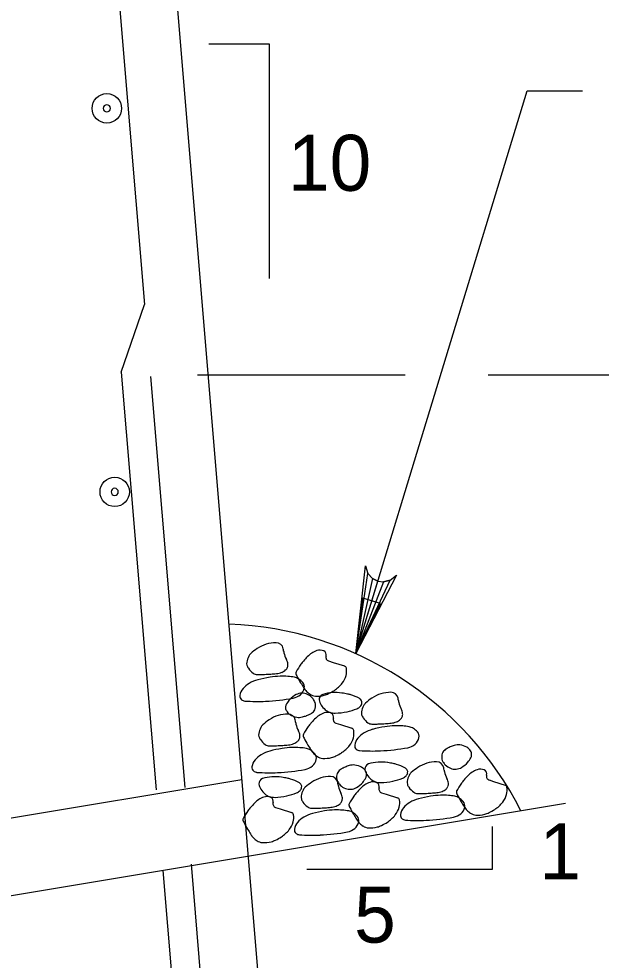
# Model space of a CAD drawing. Extents: x 634540 to 640306, y 296059 to 300275.
# Drawn here: x 639120.7 to 639151.9, y 297076.2 to 297126.7 of the extents above; entities that cross this region are included whole.
import ezdxf

# ---------------------------------------------------------------- set-up
doc = ezdxf.new("R2010")
doc.units = 0
for name, color, linetype in [('3', 7, 'Continuous'), ('5', 7, 'Continuous'), ('8', 7, 'Continuous'), ('9', 7, 'Continuous')]:
    doc.layers.add(name, color=color, linetype=linetype)

# ---------------------------------------------------------------- blocks, each defined once
blk = doc.blocks.new('B')
at = {"layer": '3'}
blk.add_circle((0, 0), 0.16, dxfattribs=at)
for start, end in [(0, 180), (180, 0)]:
    blk.add_arc((0, 0), 0.0391, start, end, dxfattribs=at)

msp = doc.modelspace()

# ---------------------------------------------------------------- linework, layer by layer
at = {"layer": '3'}
for p, q in [((639138.727, 297092.662), (639147.915, 297122.82)), ((639147.915, 297122.82), (639150.867, 297122.82)), ((639130.254, 297107.608), (639141.375, 297107.608)), ((639145.831, 297107.608), (639182.433, 297107.608))]:
    msp.add_line(p, q, dxfattribs=at)
for points in [[(639138.727, 297092.662), (639139.25, 297097.375), (639139.383, 297096.958), (639139.627, 297096.692), (639139.91, 297096.548), (639140.225, 297096.508), (639140.579, 297096.596), (639140.921, 297096.867), (639138.727, 297092.662), (639140.579, 297096.596), (639140.225, 297096.508), (639138.727, 297092.662), (639139.91, 297096.548), (639139.627, 297096.692), (639138.727, 297092.662), (639139.383, 297096.958)], [(639146.032, 297083.404), (639146.032, 297081.095), (639136.108, 297081.095)]]:
    msp.add_lwpolyline(points, dxfattribs=at)
msp.add_lwpolyline([(639140.058, 297095.344), (639139.117, 297095.629), (639138.727, 297092.662)], close=True, dxfattribs=at)
at = {"layer": '5'}
for p, q in [((639123.812, 297154.657), (639127.418, 297111.376)), ((639126.176, 297107.753), (639127.418, 297111.376)), ((639126.176, 297107.753), (639128.043, 297085.352)), ((639127.739, 297107.519), (639129.577, 297085.481)), ((639129.918, 297081.381), (639135.077, 297019.488)), ((639128.404, 297081.039), (639131.954, 297038.431))]:
    msp.add_line(p, q, dxfattribs=at)
at = {"layer": '8'}
for points in [[(639137.277, 297092.269), (639137.521, 297092.192), (639138.131, 297092)], [(639137.669, 297088.931), (639137.912, 297088.854), (639138.525, 297088.66)], [(639145.869, 297085.889), (639146.115, 297085.812), (639146.725, 297085.618)], [(639140.117, 297085.206), (639140.363, 297085.129), (639140.973, 297084.935)], [(639134.439, 297084.418), (639134.685, 297084.341), (639135.296, 297084.147)]]:
    msp.add_lwpolyline(points, dxfattribs=at)
for centre, radius, start, end in [((639134.453, 297091.467), 1.776, 89.5772, 124.1443), ((639134.463, 297092.849), 0.395, 11.4529, 89.5772), ((639135.108, 297090.501), 2.944, 124.1443, 132.7374), ((639133.528, 297092.659), 1.349, 6.1004, 11.4529), ((639135.772, 297092.899), 0.907, 186.1004, 192.6291), ((639136.188, 297092.992), 1.333, 192.6291, 208.6753), ((639137.079, 297091.599), 1.298, 109.6635, 136.4562), ((639136.812, 297092.348), 0.503, 65.9597, 109.6635), ((639136.922, 297092.596), 0.231, 342.3569, 65.9597), ((639133.197, 297092.139), 0.311, 168.4897, 199.1639), ((639134.15, 297091.945), 1.284, 153.538, 168.4897), ((639133.455, 297092.291), 0.507, 132.7374, 153.538), ((639134.408, 297092.019), 0.696, 6.391, 28.6753), ((639138.066, 297090.45), 2.801, 139.6491, 144.1424), ((639140.158, 297088.672), 5.547, 136.4562, 139.6491), ((639137.338, 297092.464), 0.205, 162.3569, 252.4715), ((639133.426, 297092.219), 0.554, 199.1639, 207.4728), ((639133.719, 297092.371), 0.884, 207.4728, 214.0468), ((639133.862, 297092.467), 1.056, 214.0468, 234.0353), ((639134.498, 297092.334), 0.726, 291.5731, 310.9894), ((639134.728, 297092.069), 0.375, 310.9894, 338.0834), ((639134.757, 297092.058), 0.344, 338.0834, 6.391), ((639138.598, 297090.066), 3.458, 144.1424, 152.1777), ((639138.087, 297091.857), 0.148, 9.0416, 72.4715), ((639137.306, 297091.733), 0.939, 344.9373, 9.0416), ((639133.957, 297089.512), 1.809, 104.9239, 120.8473), ((639133.457, 297091.91), 0.367, 234.0353, 268.2715), ((639133.548, 297094.913), 3.372, 268.2715, 270.9097), ((639135.161, 297084.993), 6.485, 99.0416, 104.9239), ((639133.462, 297100.287), 8.746, 270.9097, 272.5478), ((639133.215, 297105.856), 14.321, 272.5478, 273.846), ((639134.813, 297087.184), 4.267, 91.7881, 99.0416), ((639133.307, 297104.485), 12.947, 273.846, 275.2114), ((639134.39, 297092.607), 1.019, 275.2114, 291.5731), ((639134.811, 297087.248), 4.203, 86.0442, 91.7881), ((639134.907, 297088.635), 2.813, 79.021, 86.0442), ((639135.309, 297090.711), 0.698, 58.4341, 79.021), ((639135.66, 297091.616), 0.136, 152.1777, 193.5774), ((639135.997, 297091.697), 0.482, 193.5774, 207.4728), ((639141.328, 297094.469), 6.491, 207.4728, 211.2525), ((639135.193, 297090.521), 0.921, 40.5338, 58.4341), ((639137.106, 297091.787), 1.147, 321.7572, 344.9373), ((639133.235, 297090.32), 0.712, 139.2037, 172.3458), ((639133.729, 297089.894), 1.364, 120.8473, 139.2037), ((639135.38, 297090.927), 0.604, 309.5539, 349.0625), ((639150.608, 297100.101), 17.346, 211.2525, 212.2356), ((639135.614, 297090.882), 0.366, 349.0625, 40.5338), ((639139.131, 297092.864), 3.778, 212.2356, 214.3424), ((639136.487, 297091.057), 0.575, 214.3424, 227.6953), ((639136.077, 297093.009), 2.765, 295.7443, 303.0692), ((639136.627, 297092.164), 1.756, 303.0692, 321.7572), ((639132.774, 297090.382), 0.247, 172.3458, 230.2635), ((639132.816, 297090.432), 0.312, 230.2635, 266.2346), ((639133.487, 297100.177), 10.078, 272.3841, 280.7777), ((639136.146, 297089.31), 1.3, 136.4654, 149.2422), ((639136.142, 297089.314), 1.295, 117.4803, 136.4654), ((639135.209, 297091.135), 0.874, 280.7777, 309.5539), ((639135.863, 297089.85), 0.69, 91.376, 117.4803), ((639135.863, 297089.86), 0.681, 65.3457, 91.376), ((639137.294, 297091.943), 1.774, 227.6953, 235.2847), ((639135.821, 297089.769), 0.78, 41.057, 65.3457), ((639136.608, 297090.953), 0.569, 235.2847, 266.0442), ((639135.723, 297089.684), 0.91, 27.4728, 41.057), ((639136.668, 297091.82), 1.438, 266.0442, 285.2565), ((639137.047, 297090.212), 0.275, 106.8084, 186.6218), ((639137.355, 297090.248), 0.585, 186.6218, 200.3491), ((639137.64, 297088.248), 2.327, 81.3134, 106.8084), ((639136.691, 297091.735), 1.351, 285.2565, 295.7443), ((639137.061, 297084.457), 6.162, 78.4814, 81.3134), ((639137.835, 297088.258), 2.282, 73.8272, 78.4814), ((639137.877, 297088.4), 2.134, 61.1605, 73.8272), ((639138.734, 297089.957), 0.357, 29.8544, 61.1605), ((639141.253, 297087.845), 2.944, 124.1443, 132.7374), ((639140.598, 297088.811), 1.776, 89.5772, 124.1443), ((639140.608, 297090.193), 0.395, 11.4529, 89.5772), ((639139.673, 297090.004), 1.349, 6.1004, 11.4529), ((639133.476, 297100.454), 10.356, 266.2346, 272.3841), ((639135.311, 297089.774), 0.34, 171.9761, 209.5935), ((639135.385, 297089.763), 0.414, 149.2422, 171.9761), ((639136.134, 297089.898), 0.447, 8.0357, 27.4728), ((639136.007, 297089.88), 0.576, 337.0418, 8.0357), ((639137.473, 297090.291), 0.711, 200.3491, 212.797), ((639137.797, 297090.5), 1.097, 212.797, 230.2213), ((639137.625, 297092.599), 3.119, 281.8686, 292.039), ((639138.611, 297090.164), 0.491, 292.039, 317.8475), ((639138.697, 297090.086), 0.376, 317.8475, 347.2445), ((639140.295, 297089.289), 1.284, 153.538, 168.4897), ((639138.885, 297090.044), 0.183, 347.2445, 29.8544), ((639139.599, 297089.635), 0.507, 132.7374, 153.538), ((639141.916, 297090.243), 0.907, 186.1004, 192.6291), ((639142.332, 297090.337), 1.333, 192.6291, 208.6753), ((639140.552, 297089.363), 0.696, 6.391, 28.6753), ((639135.096, 297087.646), 1.776, 89.5772, 124.1443), ((639135.537, 297089.902), 0.6, 209.5935, 237.6667), ((639135.107, 297089.027), 0.395, 11.4529, 89.5772), ((639135.764, 297090.261), 1.024, 237.6667, 259.0544), ((639135.695, 297089.905), 0.661, 259.0544, 285.7584), ((639134.568, 297093.897), 4.81, 285.7584, 288.5059), ((639135.694, 297090.533), 1.262, 288.5059, 293.8705), ((639135.746, 297090.417), 1.135, 293.8705, 297.4803), ((639135.035, 297091.784), 2.676, 297.4803, 299.831), ((639136.165, 297089.813), 0.404, 299.831, 337.0418), ((639137.472, 297088.26), 1.298, 109.6635, 136.4562), ((639137.204, 297089.009), 0.503, 65.9597, 109.6635), ((639137.612, 297090.278), 0.808, 230.2213, 250.5601), ((639137.61, 297090.272), 0.802, 250.5601, 271.915), ((639137.315, 297089.257), 0.231, 342.3569, 65.9597), ((639137.73, 297089.125), 0.205, 162.3569, 252.4715), ((639137.515, 297093.126), 3.657, 271.915, 281.8686), ((639139.341, 297089.483), 0.311, 168.4897, 199.1639), ((639139.571, 297089.563), 0.554, 199.1639, 207.4728), ((639139.864, 297089.715), 0.884, 207.4728, 214.0468), ((639140.006, 297089.811), 1.056, 214.0468, 234.0353), ((639140.872, 297089.414), 0.375, 310.9894, 338.0834), ((639140.901, 297089.402), 0.344, 338.0834, 6.391), ((639134.793, 297088.123), 1.284, 153.538, 168.4897), ((639134.098, 297088.469), 0.507, 132.7374, 153.538), ((639135.752, 297086.68), 2.944, 124.1443, 132.7374), ((639134.172, 297088.838), 1.349, 6.1004, 11.4529), ((639136.415, 297089.078), 0.907, 186.1004, 192.6291), ((639136.831, 297089.171), 1.333, 192.6291, 208.6753), ((639138.99, 297086.727), 3.458, 144.1424, 152.1777), ((639138.459, 297087.111), 2.801, 139.6491, 144.1424), ((639140.551, 297085.334), 5.547, 136.4562, 139.6491), ((639139.601, 297089.254), 0.367, 234.0353, 268.2715), ((639139.692, 297092.257), 3.372, 268.2715, 270.9097), ((639141.306, 297082.337), 6.485, 99.0416, 104.9239), ((639139.607, 297097.631), 8.746, 270.9097, 272.5478), ((639139.359, 297103.2), 14.321, 272.5478, 273.846), ((639140.957, 297084.528), 4.267, 91.7881, 99.0416), ((639139.451, 297101.829), 12.947, 273.846, 275.2114), ((639140.534, 297089.951), 1.019, 275.2114, 291.5731), ((639140.955, 297084.592), 4.203, 86.0442, 91.7881), ((639140.642, 297089.678), 0.726, 291.5731, 310.9894), ((639141.051, 297085.979), 2.813, 79.021, 86.0442), ((639141.454, 297088.055), 0.698, 58.4341, 79.021), ((639133.84, 297088.318), 0.311, 168.4897, 199.1639), ((639134.069, 297088.397), 0.554, 199.1639, 207.4728), ((639135.051, 297088.197), 0.696, 6.391, 28.6753), ((639135.4, 297088.236), 0.344, 338.0834, 6.391), ((639136.053, 297088.277), 0.136, 152.1777, 193.5774), ((639136.39, 297088.358), 0.482, 193.5774, 207.4728), ((639138.479, 297088.518), 0.148, 9.0416, 72.4715), ((639137.699, 297088.394), 0.939, 344.9373, 9.0416), ((639139.873, 297087.238), 1.364, 120.8473, 139.2037), ((639140.101, 297086.856), 1.809, 104.9239, 120.8473), ((639141.337, 297087.866), 0.921, 40.5338, 58.4341), ((639141.759, 297088.226), 0.366, 349.0625, 40.5338), ((639134.363, 297088.55), 0.884, 207.4728, 214.0468), ((639134.505, 297088.646), 1.056, 214.0468, 234.0353), ((639134.1, 297088.088), 0.367, 234.0353, 268.2715), ((639134.191, 297091.092), 3.372, 268.2715, 270.9097), ((639134.106, 297096.465), 8.746, 270.9097, 272.5478), ((639133.858, 297102.034), 14.321, 272.5478, 273.846), ((639133.95, 297100.663), 12.947, 273.846, 275.2114), ((639135.033, 297088.785), 1.019, 275.2114, 291.5731), ((639135.141, 297088.512), 0.726, 291.5731, 310.9894), ((639135.371, 297088.248), 0.375, 310.9894, 338.0834), ((639141.721, 297091.13), 6.491, 207.4728, 211.2525), ((639151, 297096.762), 17.346, 211.2525, 212.2356), ((639137.019, 297088.825), 1.756, 303.0692, 321.7572), ((639137.498, 297088.448), 1.147, 321.7572, 344.9373), ((639138.919, 297087.726), 0.247, 172.3458, 230.2635), ((639139.379, 297087.664), 0.712, 139.2037, 172.3458), ((639141.353, 297088.479), 0.874, 280.7777, 309.5539), ((639141.525, 297088.271), 0.604, 309.5539, 349.0625), ((639144.256, 297086.486), 1.262, 111.6288, 116.9933), ((639145.564, 297083.188), 4.81, 108.8812, 111.6288), ((639144.221, 297087.113), 0.661, 82.1773, 108.8812), ((639144.172, 297086.754), 1.024, 60.7895, 82.1773), ((639134.372, 297086.073), 1.364, 120.8473, 139.2037), ((639134.6, 297085.691), 1.809, 104.9239, 120.8473), ((639135.804, 297081.172), 6.485, 99.0416, 104.9239), ((639135.456, 297083.363), 4.267, 91.7881, 99.0416), ((639135.454, 297083.426), 4.203, 86.0442, 91.7881), ((639135.55, 297084.814), 2.813, 79.021, 86.0442), ((639135.953, 297086.89), 0.698, 58.4341, 79.021), ((639135.836, 297086.7), 0.921, 40.5338, 58.4341), ((639139.524, 297089.525), 3.778, 212.2356, 214.3424), ((639136.879, 297087.718), 0.575, 214.3424, 227.6953), ((639137.686, 297088.604), 1.774, 227.6953, 235.2847), ((639136.257, 297087.06), 0.366, 349.0625, 40.5338), ((639137.083, 297088.397), 1.351, 285.2565, 295.7443), ((639136.469, 297089.67), 2.765, 295.7443, 303.0692), ((639138.961, 297087.777), 0.312, 230.2635, 266.2346), ((639139.62, 297097.798), 10.356, 266.2346, 272.3841), ((639139.632, 297097.521), 10.078, 272.3841, 280.7777), ((639143.909, 297087.121), 0.576, 160.1647, 191.1585), ((639143.747, 297087.179), 0.404, 122.9538, 160.1647), ((639144.983, 297085.273), 2.676, 120.6031, 122.9538), ((639144.198, 297086.599), 1.135, 116.9933, 120.6031), ((639144.379, 297087.124), 0.6, 32.7163, 60.7895), ((639144.598, 297087.265), 0.34, 355.0989, 32.7163), ((639144.524, 297087.271), 0.414, 332.365, 355.0989), ((639133.878, 297086.499), 0.712, 139.2037, 172.3458), ((639136.024, 297087.106), 0.604, 309.5539, 349.0625), ((639137, 297087.615), 0.569, 235.2847, 266.0442), ((639137.06, 297088.481), 1.438, 266.0442, 285.2565), ((639139.938, 297082.108), 4.81, 108.8812, 111.6288), ((639138.596, 297086.033), 0.661, 82.1773, 108.8812), ((639138.546, 297085.673), 1.024, 60.7895, 82.1773), ((639139.496, 297086.487), 0.275, 106.8084, 186.6218), ((639140.089, 297084.523), 2.327, 81.3134, 106.8084), ((639139.51, 297080.732), 6.162, 78.4814, 81.3134), ((639140.284, 297084.533), 2.282, 73.8272, 78.4814), ((639140.326, 297084.675), 2.134, 61.1605, 73.8272), ((639143.046, 297085.086), 1.776, 89.5772, 124.1443), ((639143.057, 297086.468), 0.395, 11.4529, 89.5772), ((639143.782, 297087.096), 0.447, 191.1585, 210.5956), ((639144.181, 297087.332), 0.91, 210.5956, 224.1798), ((639144.088, 297087.241), 0.78, 224.1798, 248.4685), ((639143.743, 297087.678), 1.295, 300.6031, 319.5882), ((639143.739, 297087.682), 1.3, 319.5882, 332.365), ((639133.418, 297086.561), 0.247, 172.3458, 230.2635), ((639133.459, 297086.611), 0.312, 230.2635, 266.2346), ((639134.119, 297096.632), 10.356, 266.2346, 272.3841), ((639134.131, 297096.355), 10.078, 272.3841, 280.7777), ((639135.852, 297087.314), 0.874, 280.7777, 309.5539), ((639138.283, 297086.041), 0.576, 160.1647, 191.1585), ((639138.121, 297086.099), 0.404, 122.9538, 160.1647), ((639139.357, 297084.193), 2.676, 120.6031, 122.9538), ((639138.573, 297085.519), 1.135, 116.9933, 120.6031), ((639138.631, 297085.405), 1.262, 111.6288, 116.9933), ((639138.753, 297086.044), 0.6, 32.7163, 60.7895), ((639139.804, 297086.523), 0.585, 186.6218, 200.3491), ((639139.922, 297086.566), 0.711, 200.3491, 212.797), ((639138.973, 297086.184), 0.34, 355.0989, 32.7163), ((639138.898, 297086.191), 0.414, 332.365, 355.0989), ((639140.246, 297086.775), 1.097, 212.797, 230.2213), ((639141.183, 297086.232), 0.357, 29.8544, 61.1605), ((639141.146, 297086.361), 0.376, 317.8475, 347.2445), ((639141.333, 297086.319), 0.183, 347.2445, 29.8544), ((639142.048, 297085.91), 0.507, 132.7374, 153.538), ((639143.702, 297084.12), 2.944, 124.1443, 132.7374), ((639142.121, 297086.278), 1.349, 6.1004, 11.4529), ((639144.365, 297086.518), 0.907, 186.1004, 192.6291), ((639144.781, 297086.611), 1.333, 192.6291, 208.6753), ((639144.051, 297087.149), 0.681, 248.4685, 274.4988), ((639144.051, 297087.158), 0.69, 274.4988, 300.6031), ((639145.672, 297085.218), 1.298, 109.6635, 136.4562), ((639145.405, 297085.967), 0.503, 65.9597, 109.6635), ((639145.515, 297086.215), 0.231, 342.3569, 65.9597), ((639145.931, 297086.083), 0.205, 162.3569, 252.4715), ((639133.818, 297085.699), 0.275, 106.8084, 186.6218), ((639134.126, 297085.735), 0.585, 186.6218, 200.3491), ((639134.411, 297083.736), 2.327, 81.3134, 106.8084), ((639133.832, 297079.944), 6.162, 78.4814, 81.3134), ((639134.607, 297083.746), 2.282, 73.8272, 78.4814), ((639134.648, 297083.888), 2.134, 61.1605, 73.8272), ((639135.506, 297085.445), 0.357, 29.8544, 61.1605), ((639138.024, 297083.333), 2.944, 124.1443, 132.7374), ((639137.369, 297084.299), 1.776, 89.5772, 124.1443), ((639137.379, 297085.681), 0.395, 11.4529, 89.5772), ((639138.157, 297086.016), 0.447, 191.1585, 210.5956), ((639136.444, 297085.491), 1.349, 6.1004, 11.4529), ((639138.556, 297086.252), 0.91, 210.5956, 224.1798), ((639138.118, 297086.598), 1.295, 300.6031, 319.5882), ((639139.92, 297084.535), 1.298, 109.6635, 136.4562), ((639138.113, 297086.602), 1.3, 319.5882, 332.365), ((639139.653, 297085.284), 0.503, 65.9597, 109.6635), ((639140.061, 297086.553), 0.808, 230.2213, 250.5601), ((639140.059, 297086.547), 0.802, 250.5601, 271.915), ((639139.763, 297085.532), 0.231, 342.3569, 65.9597), ((639139.963, 297089.401), 3.657, 271.915, 281.8686), ((639140.074, 297088.874), 3.119, 281.8686, 292.039), ((639141.06, 297086.439), 0.491, 292.039, 317.8475), ((639141.79, 297085.758), 0.311, 168.4897, 199.1639), ((639142.743, 297085.564), 1.284, 153.538, 168.4897), ((639142.019, 297085.838), 0.554, 199.1639, 207.4728), ((639143.001, 297085.638), 0.696, 6.391, 28.6753), ((639143.35, 297085.677), 0.344, 338.0834, 6.391), ((639147.191, 297083.685), 3.458, 144.1424, 152.1777), ((639146.659, 297084.069), 2.801, 139.6491, 144.1424), ((639148.752, 297082.292), 5.547, 136.4562, 139.6491), ((639134.244, 297085.779), 0.711, 200.3491, 212.797), ((639134.569, 297085.988), 1.097, 212.797, 230.2213), ((639134.383, 297085.765), 0.808, 230.2213, 250.5601), ((639134.397, 297088.087), 3.119, 281.8686, 292.039), ((639135.383, 297085.651), 0.491, 292.039, 317.8475), ((639135.468, 297085.574), 0.376, 317.8475, 347.2445), ((639137.066, 297084.777), 1.284, 153.538, 168.4897), ((639135.656, 297085.531), 0.183, 347.2445, 29.8544), ((639136.371, 297085.123), 0.507, 132.7374, 153.538), ((639138.687, 297085.731), 0.907, 186.1004, 192.6291), ((639139.103, 297085.824), 1.333, 192.6291, 208.6753), ((639138.462, 297086.161), 0.78, 224.1798, 248.4685), ((639137.323, 297084.85), 0.696, 6.391, 28.6753), ((639138.426, 297086.069), 0.681, 248.4685, 274.4988), ((639138.425, 297086.078), 0.69, 274.4988, 300.6031), ((639140.907, 297083.386), 2.801, 139.6491, 144.1424), ((639143, 297081.609), 5.547, 136.4562, 139.6491), ((639140.179, 297085.4), 0.205, 162.3569, 252.4715), ((639142.313, 297085.99), 0.884, 207.4728, 214.0468), ((639142.455, 297086.086), 1.056, 214.0468, 234.0353), ((639142.05, 297085.529), 0.367, 234.0353, 268.2715), ((639142.141, 297088.532), 3.372, 268.2715, 270.9097), ((639142.056, 297093.906), 8.746, 270.9097, 272.5478), ((639141.808, 297099.475), 14.321, 272.5478, 273.846), ((639141.9, 297098.104), 12.947, 273.846, 275.2114), ((639142.983, 297086.226), 1.019, 275.2114, 291.5731), ((639143.091, 297085.953), 0.726, 291.5731, 310.9894), ((639143.321, 297085.688), 0.375, 310.9894, 338.0834), ((639144.254, 297085.235), 0.136, 152.1777, 193.5774), ((639144.591, 297085.317), 0.482, 193.5774, 207.4728), ((639146.68, 297085.476), 0.148, 9.0416, 72.4715), ((639145.899, 297085.352), 0.939, 344.9373, 9.0416), ((639137.322, 297080.821), 5.547, 136.4562, 139.6491), ((639134.243, 297083.748), 1.298, 109.6635, 136.4562), ((639133.975, 297084.497), 0.503, 65.9597, 109.6635), ((639134.382, 297085.76), 0.802, 250.5601, 271.915), ((639134.086, 297084.745), 0.231, 342.3569, 65.9597), ((639134.502, 297084.613), 0.205, 162.3569, 252.4715), ((639134.286, 297088.613), 3.657, 271.915, 281.8686), ((639136.112, 297084.971), 0.311, 168.4897, 199.1639), ((639136.342, 297085.051), 0.554, 199.1639, 207.4728), ((639136.635, 297085.203), 0.884, 207.4728, 214.0468), ((639136.777, 297085.299), 1.056, 214.0468, 234.0353), ((639137.644, 297084.901), 0.375, 310.9894, 338.0834), ((639137.672, 297084.89), 0.344, 338.0834, 6.391), ((639141.439, 297083.002), 3.458, 144.1424, 152.1777), ((639140.928, 297084.793), 0.148, 9.0416, 72.4715), ((639140.147, 297084.669), 0.939, 344.9373, 9.0416), ((639142.322, 297083.513), 1.364, 120.8473, 139.2037), ((639142.55, 297083.131), 1.809, 104.9239, 120.8473), ((639143.754, 297078.612), 6.485, 99.0416, 104.9239), ((639143.406, 297080.803), 4.267, 91.7881, 99.0416), ((639143.404, 297080.867), 4.203, 86.0442, 91.7881), ((639143.5, 297082.254), 2.813, 79.021, 86.0442), ((639143.903, 297084.33), 0.698, 58.4341, 79.021), ((639149.922, 297088.088), 6.491, 207.4728, 211.2525), ((639143.786, 297084.14), 0.921, 40.5338, 58.4341), ((639159.201, 297093.72), 17.346, 211.2525, 212.2356), ((639144.207, 297084.501), 0.366, 349.0625, 40.5338), ((639145.22, 297085.783), 1.756, 303.0692, 321.7572), ((639145.699, 297085.406), 1.147, 321.7572, 344.9373), ((639135.762, 297082.214), 3.458, 144.1424, 152.1777), ((639135.23, 297082.599), 2.801, 139.6491, 144.1424), ((639135.251, 297084.006), 0.148, 9.0416, 72.4715), ((639136.373, 297084.742), 0.367, 234.0353, 268.2715), ((639136.463, 297087.745), 3.372, 268.2715, 270.9097), ((639138.077, 297077.825), 6.485, 99.0416, 104.9239), ((639136.378, 297093.119), 8.746, 270.9097, 272.5478), ((639136.13, 297098.688), 14.321, 272.5478, 273.846), ((639137.728, 297080.016), 4.267, 91.7881, 99.0416), ((639136.223, 297097.317), 12.947, 273.846, 275.2114), ((639137.306, 297085.439), 1.019, 275.2114, 291.5731), ((639137.726, 297080.08), 4.203, 86.0442, 91.7881), ((639137.414, 297085.166), 0.726, 291.5731, 310.9894), ((639137.822, 297081.467), 2.813, 79.021, 86.0442), ((639138.225, 297083.543), 0.698, 58.4341, 79.021), ((639138.502, 297084.552), 0.136, 152.1777, 193.5774), ((639138.839, 297084.633), 0.482, 193.5774, 207.4728), ((639144.17, 297087.405), 6.491, 207.4728, 211.2525), ((639138.108, 297083.353), 0.921, 40.5338, 58.4341), ((639139.947, 297084.723), 1.147, 321.7572, 344.9373), ((639141.828, 297083.939), 0.712, 139.2037, 172.3458), ((639143.974, 297084.546), 0.604, 309.5539, 349.0625), ((639147.725, 297086.483), 3.778, 212.2356, 214.3424), ((639145.08, 297084.676), 0.575, 214.3424, 227.6953), ((639145.887, 297085.563), 1.774, 227.6953, 235.2847), ((639145.284, 297085.355), 1.351, 285.2565, 295.7443), ((639144.67, 297086.628), 2.765, 295.7443, 303.0692), ((639132.824, 297083.765), 0.136, 152.1777, 193.5774), ((639133.161, 297083.846), 0.482, 193.5774, 207.4728), ((639138.492, 297086.618), 6.491, 207.4728, 211.2525), ((639134.269, 297083.936), 1.147, 321.7572, 344.9373), ((639134.47, 297083.882), 0.939, 344.9373, 9.0416), ((639136.645, 297082.726), 1.364, 120.8473, 139.2037), ((639136.873, 297082.344), 1.809, 104.9239, 120.8473), ((639153.449, 297093.037), 17.346, 211.2525, 212.2356), ((639138.296, 297083.759), 0.604, 309.5539, 349.0625), ((639141.973, 297085.8), 3.778, 212.2356, 214.3424), ((639138.53, 297083.714), 0.366, 349.0625, 40.5338), ((639139.328, 297083.993), 0.575, 214.3424, 227.6953), ((639138.918, 297085.945), 2.765, 295.7443, 303.0692), ((639139.468, 297085.1), 1.756, 303.0692, 321.7572), ((639141.368, 297084.001), 0.247, 172.3458, 230.2635), ((639141.409, 297084.052), 0.312, 230.2635, 266.2346), ((639142.069, 297094.073), 10.356, 266.2346, 272.3841), ((639142.08, 297093.796), 10.078, 272.3841, 280.7777), ((639143.802, 297084.754), 0.874, 280.7777, 309.5539), ((639145.201, 297084.573), 0.569, 235.2847, 266.0442), ((639145.261, 297085.44), 1.438, 266.0442, 285.2565), ((639147.772, 297092.249), 17.346, 211.2525, 212.2356), ((639133.791, 297084.313), 1.756, 303.0692, 321.7572), ((639135.69, 297083.214), 0.247, 172.3458, 230.2635), ((639136.151, 297083.152), 0.712, 139.2037, 172.3458), ((639138.124, 297083.967), 0.874, 280.7777, 309.5539), ((639140.135, 297084.879), 1.774, 227.6953, 235.2847), ((639139.449, 297083.89), 0.569, 235.2847, 266.0442), ((639139.509, 297084.756), 1.438, 266.0442, 285.2565), ((639139.532, 297084.672), 1.351, 285.2565, 295.7443), ((639136.295, 297085.012), 3.778, 212.2356, 214.3424), ((639133.65, 297083.205), 0.575, 214.3424, 227.6953), ((639134.457, 297084.092), 1.774, 227.6953, 235.2847), ((639133.772, 297083.102), 0.569, 235.2847, 266.0442), ((639133.855, 297083.884), 1.351, 285.2565, 295.7443), ((639133.24, 297085.158), 2.765, 295.7443, 303.0692), ((639135.732, 297083.264), 0.312, 230.2635, 266.2346), ((639136.392, 297093.286), 10.356, 266.2346, 272.3841), ((639136.403, 297093.009), 10.078, 272.3841, 280.7777), ((639133.832, 297083.969), 1.438, 266.0442, 285.2565)]:
    msp.add_arc(centre, radius, start, end, dxfattribs=at)
at = {"layer": '9'}
for p, q in [((639125.293, 297173.916), (639136.712, 297036.893)), ((639132.629, 297085.9), (639106.838, 297081.602)), ((639149.955, 297084.631), (639106.838, 297077.445))]:
    msp.add_line(p, q, dxfattribs=at)
msp.add_lwpolyline([(639130.856, 297125.345), (639134.087, 297125.345), (639134.087, 297112.761)], dxfattribs=at)
msp.add_arc((639131.232, 297075.93), 18.332, 26.9324, 87.7453, dxfattribs=at)

# ---------------------------------------------------------------- block references
at = {"layer": '3', "xscale": 4.921475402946, "yscale": 4.921475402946, "rotation": 90}
for p in [(639125.403, 297121.889), (639125.824, 297101.33)]:
    msp.add_blockref('B', p, dxfattribs=at)

# ---------------------------------------------------------------- texts
at = {"layer": '3'}
for s, height, p in [('10', 3.0001, (639135.1, 297117.47)), ('1', 3, (639148.567, 297080.562)), ('5', 3, (639138.644, 297077.172))]:
    msp.add_text(s, height=height, dxfattribs=at).set_placement(p)

doc.saveas('drawing.dxf')
